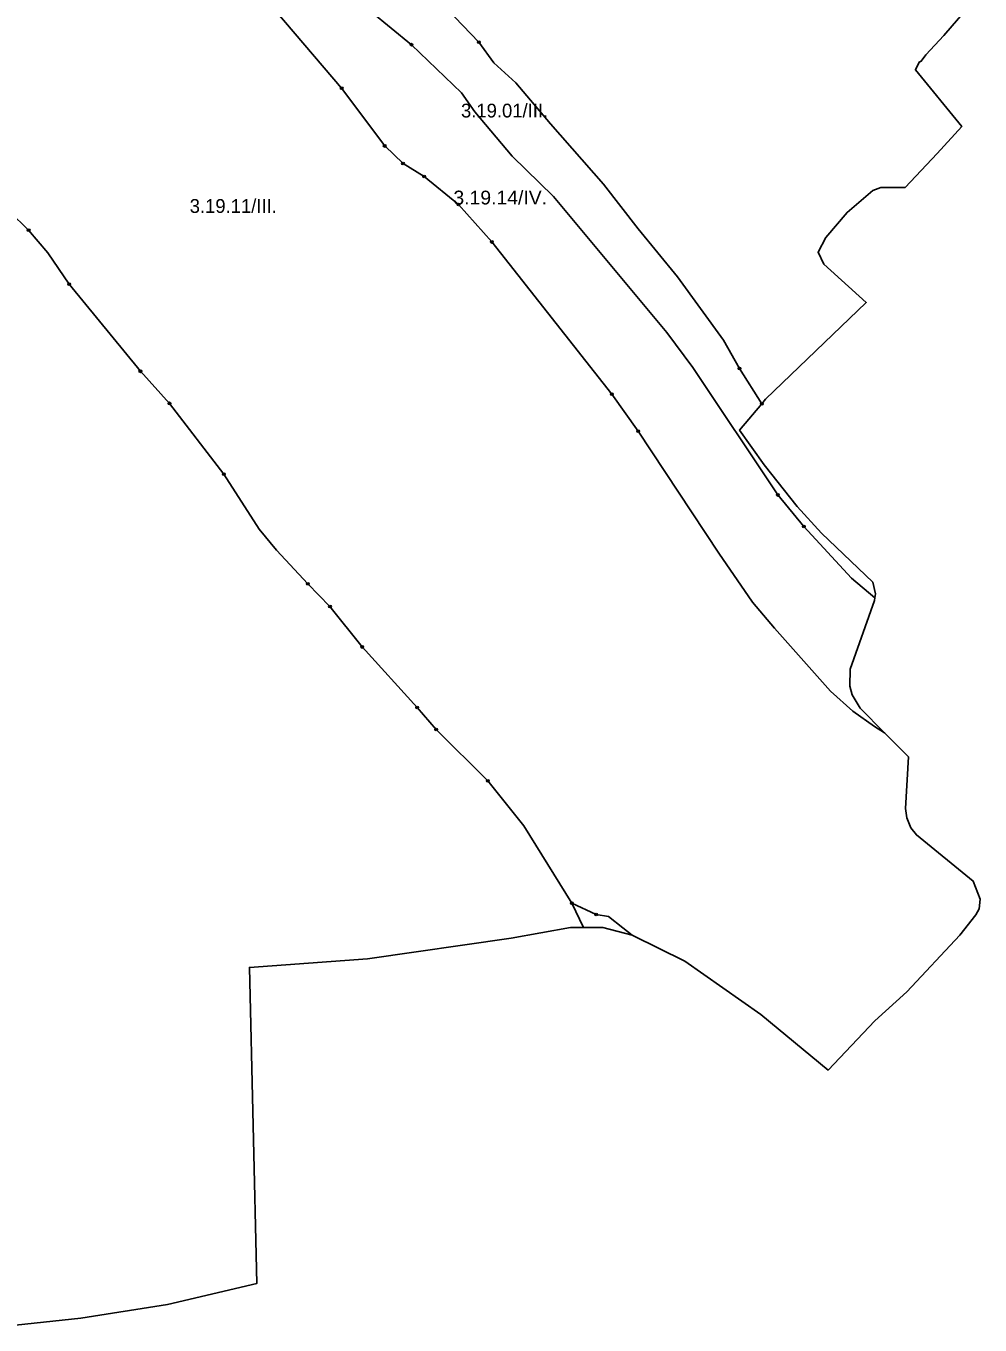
# Model space of a CAD drawing. Extents: x -650455 to -642254, y -1075222 to -1066610.
# Drawn here: x -644416 to -643724, y -1073642 to -1072701 of the extents above; entities that cross this region are included whole.
import ezdxf
from ezdxf.enums import TextEntityAlignment as Align

# ---------------------------------------------------------------- set-up
doc = ezdxf.new("R2010")
doc.units = 0
doc.header["$LTSCALE"] = 4
doc.header["$PDMODE"] = 32
doc.header["$PDSIZE"] = 2
for name, color, linetype, lineweight in [('1', 7, 'Continuous', 25), ('11', 7, 'Continuous', 13), ('13', 7, 'Continuous', 13), ('14', 7, 'Continuous', 13)]:
    doc.layers.add(name, color=color, linetype=linetype, lineweight=lineweight)
doc.layers.add('2', color=7, linetype='Continuous')

msp = doc.modelspace()

# ---------------------------------------------------------------- linework, layer by layer
at = {"layer": '1'}
for points in [[(-644133.59, -1072663.941), (-644087.515, -1072712.377), (-644076.499, -1072727.239), (-644060.762, -1072741.927), (-644035.408, -1072771.653), (-643997.027, -1072815.367), (-643971.935, -1072847.715), (-643943.434, -1072882.512), (-643910.123, -1072928.499), (-643898.495, -1072948.957)], [(-643734.991, -1072689.776), (-643750.231, -1072707.416), (-643763.214, -1072721.526), (-643766.742, -1072726.043), (-643768.011, -1072726.748), (-643770.864, -1072732.304), (-643737.297, -1072773.436), (-643755.036, -1072793.028), (-643778.183, -1072817.707), (-643795.921, -1072817.707), (-643801.762, -1072819.98), (-643820.366, -1072835.782), (-643835.725, -1072853.968), (-643841.349, -1072864.684), (-643837.239, -1072873.344), (-643806.535, -1072901.023), (-643879.504, -1072971.156), (-643882.299, -1072974.5), (-643898.495, -1072948.957), (-643910.123, -1072928.499), (-643943.434, -1072882.512), (-643971.935, -1072847.715), (-643997.027, -1072815.367), (-644035.408, -1072771.653), (-644060.762, -1072741.927), (-644076.499, -1072727.239), (-644087.515, -1072712.377), (-644133.59, -1072663.941)], [(-644234.796, -1072689.872), (-644186.973, -1072745.651), (-644155.761, -1072787.617), (-644142.471, -1072800.381), (-644127.172, -1072809.824), (-644102.167, -1072830.107), (-644078.124, -1072857.21), (-643990.959, -1072967.544), (-643971.987, -1072994.472), (-643913.497, -1073082.949), (-643888.93, -1073118.445), (-643872.93, -1073137.155), (-643832.539, -1073182.792), (-643816.189, -1073197.48), (-643800.627, -1073208.496), (-643793.212, -1073213.013), (-643775.773, -1073230.523), (-643778.031, -1073267.918), (-643777.184, -1073274.69), (-643774.079, -1073282.028), (-643769.987, -1073286.968), (-643729.064, -1073320.694)], [(-644165.902, -1072690.047), (-644136.264, -1072714.177), (-644100.069, -1072749.148), (-644090.364, -1072762.787), (-644063.262, -1072794.961), (-644033.274, -1072824.162), (-643951.179, -1072922.956), (-643932.382, -1072948.31), (-643870.57, -1073040.634), (-643851.773, -1073063.54), (-643817.151, -1073100.96), (-643800.254, -1073115.142), (-643800.608, -1073117.208), (-643818.106, -1073166.881), (-643818.53, -1073179.298), (-643816.837, -1073185.507), (-643810.91, -1073195.243), (-643793.212, -1073213.013), (-643800.627, -1073208.496), (-643816.189, -1073197.48), (-643832.539, -1073182.792), (-643872.93, -1073137.155), (-643888.93, -1073118.445), (-643913.497, -1073082.949), (-643971.987, -1072994.472), (-643990.959, -1072967.544), (-644078.124, -1072857.21), (-644102.167, -1072830.107), (-644127.172, -1072809.824), (-644142.471, -1072800.381), (-644155.761, -1072787.617), (-644186.973, -1072745.651), (-644234.796, -1072689.872)], [(-643799.762, -1073112.269), (-643800.254, -1073115.142), (-643817.151, -1073100.96), (-643851.773, -1073063.54), (-643870.57, -1073040.634), (-643932.382, -1072948.31), (-643951.179, -1072922.956), (-644033.274, -1072824.162), (-644063.262, -1072794.961), (-644090.364, -1072762.787), (-644100.069, -1072749.148), (-644136.264, -1072714.177), (-644165.902, -1072690.047)], [(-644427.764, -1072835.165), (-644413.997, -1072848.687), (-644400.183, -1072865.124), (-644384.621, -1072887.855), (-644332.951, -1072950.978), (-644311.793, -1072974.234), (-644272.363, -1073025.642), (-644246.747, -1073065.334), (-644234.157, -1073080.721), (-644211.513, -1073105.026), (-644195.427, -1073121.463), (-644172.083, -1073150.839), (-644132.216, -1073194.728), (-644118.49, -1073210.64), (-644080.896, -1073247.884), (-644054.929, -1073280.582), (-644020.045, -1073336.536), (-644011.677, -1073354.192), (-644020.886, -1073354.137), (-644064.067, -1073362.039), (-644168.209, -1073376.856), (-644253.864, -1073383.206), (-644248.437, -1073612.322), (-644313.273, -1073627.474), (-644376.209, -1073637.35), (-644423.623, -1073642.431)], [(-643729.064, -1073320.694), (-643723.984, -1073333.675), (-643724.69, -1073340.59), (-643726.947, -1073344.965), (-643738.66, -1073359.782), (-643777.043, -1073400.846), (-643800.326, -1073422.013), (-643834.173, -1073457.614), (-643882.878, -1073417.215), (-643938.194, -1073378.691), (-643975.73, -1073359.923), (-643976.242, -1073359.79), (-643983.062, -1073354.416), (-643993.414, -1073346.315), (-644002.385, -1073344.755), (-644020.045, -1073336.536), (-644054.929, -1073280.582), (-644080.896, -1073247.884), (-644118.49, -1073210.64), (-644132.216, -1073194.728), (-644172.083, -1073150.839), (-644195.427, -1073121.463), (-644211.513, -1073105.026), (-644234.157, -1073080.721), (-644246.747, -1073065.334), (-644272.363, -1073025.642), (-644311.793, -1072974.234), (-644332.951, -1072950.978), (-644384.621, -1072887.855), (-644400.183, -1072865.124), (-644413.997, -1072848.687), (-644427.764, -1072835.165)], [(-643898.495, -1072948.957), (-643882.299, -1072974.5), (-643898.324, -1072993.671), (-643880.62, -1073018.853), (-643856.489, -1073048.91), (-643838.991, -1073068.243), (-643801.737, -1073103.803), (-643799.762, -1073112.269)]]:
    msp.add_lwpolyline(points, dxfattribs=at)
msp.add_lwpolyline([(-643983.062, -1073354.416), (-643976.242, -1073359.79), (-643997.462, -1073354.278), (-644011.677, -1073354.192), (-644020.045, -1073336.536), (-644002.385, -1073344.755), (-643993.414, -1073346.315)], close=True, dxfattribs=at)
at = {"layer": '11'}
for points in [[(-644133.59, -1072663.941), (-644087.515, -1072712.377), (-644076.499, -1072727.239), (-644060.762, -1072741.927), (-644035.408, -1072771.653)], [(-643882.299, -1072974.5), (-643879.504, -1072971.156), (-643806.535, -1072901.023), (-643837.239, -1072873.344), (-643841.349, -1072864.684), (-643835.725, -1072853.968), (-643820.366, -1072835.782), (-643801.762, -1072819.98), (-643795.921, -1072817.707), (-643778.183, -1072817.707), (-643755.036, -1072793.028), (-643737.297, -1072773.436), (-643770.864, -1072732.304), (-643768.011, -1072726.748), (-643766.742, -1072726.043), (-643763.214, -1072721.526), (-643750.231, -1072707.416), (-643734.991, -1072689.776)], [(-644035.408, -1072771.653), (-643997.027, -1072815.367), (-643971.935, -1072847.715), (-643943.434, -1072882.512), (-643910.123, -1072928.499), (-643898.495, -1072948.957), (-643882.299, -1072974.5)]]:
    msp.add_lwpolyline(points, dxfattribs=at)
msp.add_point((-643882.299, -1072974.5), dxfattribs=at)
at = {"layer": '13'}
for p, q in [((-644155.761, -1072787.617), (-644186.973, -1072745.651)), ((-644142.471, -1072800.381), (-644155.761, -1072787.617)), ((-644311.793, -1072974.234), (-644272.363, -1073025.642)), ((-644195.427, -1073121.463), (-644172.083, -1073150.839)), ((-644172.083, -1073150.839), (-644132.216, -1073194.728)), ((-644132.216, -1073194.728), (-644118.49, -1073210.64)), ((-644118.49, -1073210.64), (-644080.896, -1073247.884)), ((-644020.045, -1073336.536), (-644002.385, -1073344.755))]:
    msp.add_line(p, q, dxfattribs=at)
for points in [[(-644087.515, -1072712.377), (-644133.59, -1072663.941), (-644141.983, -1072654.499), (-644148.278, -1072649.253), (-644177.392, -1072620.927), (-644195.402, -1072601.518), (-644209.565, -1072583.682), (-644221.018, -1072567.071), (-644234.482, -1072548.536), (-644249.695, -1072522.483), (-644262.896, -1072504.647), (-644270.415, -1072497.128), (-644262.896, -1072532.799), (-644259.8, -1072552.61), (-644255.953, -1072567.997), (-644245.025, -1072592.302), (-644236.282, -1072610.662), (-644215.824, -1072635.667), (-644184.262, -1072673.086), (-644165.902, -1072690.047), (-644136.264, -1072714.177)], [(-644186.973, -1072745.651), (-644234.796, -1072689.872), (-644258.227, -1072667.141), (-644304.476, -1072617.307)], [(-644136.264, -1072714.177), (-644100.069, -1072749.148), (-644090.364, -1072762.787), (-644063.262, -1072794.961), (-644033.274, -1072824.162), (-643951.179, -1072922.956), (-643932.382, -1072948.31), (-643870.57, -1073040.634), (-643851.773, -1073063.54)], [(-643898.495, -1072948.957), (-643910.123, -1072928.499), (-643943.434, -1072882.512), (-643971.935, -1072847.715), (-643997.027, -1072815.367), (-644035.408, -1072771.653), (-644060.762, -1072741.927), (-644076.499, -1072727.239), (-644087.515, -1072712.377)], [(-644102.167, -1072830.107), (-644127.172, -1072809.824), (-644142.471, -1072800.381)], [(-644424.966, -1072822.225), (-644427.764, -1072835.165), (-644413.997, -1072848.687)], [(-643971.987, -1072994.472), (-643990.959, -1072967.544), (-644078.124, -1072857.21), (-644102.167, -1072830.107)], [(-644332.951, -1072950.978), (-644384.621, -1072887.855), (-644400.183, -1072865.124), (-644413.997, -1072848.687), (-644427.764, -1072835.165)], [(-644413.997, -1072848.687), (-644400.183, -1072865.124), (-644384.621, -1072887.855)], [(-644384.621, -1072887.855), (-644332.951, -1072950.978), (-644311.793, -1072974.234)], [(-644211.513, -1073105.026), (-644234.157, -1073080.721), (-644246.747, -1073065.334), (-644272.363, -1073025.642), (-644311.793, -1072974.234), (-644332.951, -1072950.978)], [(-643851.773, -1073063.54), (-643817.151, -1073100.96), (-643800.254, -1073115.142), (-643799.762, -1073112.269), (-643801.737, -1073103.803), (-643838.991, -1073068.243), (-643856.489, -1073048.91), (-643880.62, -1073018.853), (-643898.324, -1072993.671), (-643882.299, -1072974.5), (-643898.495, -1072948.957)], [(-644002.385, -1073344.755), (-643993.414, -1073346.315), (-643983.062, -1073354.416), (-643976.242, -1073359.79), (-643975.73, -1073359.923), (-643938.194, -1073378.691), (-643882.878, -1073417.215), (-643834.173, -1073457.614), (-643800.326, -1073422.013), (-643777.043, -1073400.846), (-643738.66, -1073359.782), (-643726.947, -1073344.965), (-643724.69, -1073340.59), (-643723.984, -1073333.675), (-643729.064, -1073320.694), (-643769.987, -1073286.968), (-643774.079, -1073282.028), (-643777.184, -1073274.69), (-643778.031, -1073267.918), (-643775.773, -1073230.523), (-643793.212, -1073213.013), (-643800.627, -1073208.496), (-643816.189, -1073197.48), (-643832.539, -1073182.792), (-643872.93, -1073137.155), (-643888.93, -1073118.445), (-643913.497, -1073082.949), (-643971.987, -1072994.472)], [(-644272.363, -1073025.642), (-644246.747, -1073065.334), (-644234.157, -1073080.721), (-644211.513, -1073105.026), (-644195.427, -1073121.463)], [(-644423.623, -1073642.431), (-644376.209, -1073637.35), (-644313.273, -1073627.474), (-644248.437, -1073612.322), (-644253.864, -1073383.206), (-644168.209, -1073376.856), (-644064.067, -1073362.039), (-644020.886, -1073354.137), (-644011.677, -1073354.192), (-644020.045, -1073336.536), (-644054.929, -1073280.582), (-644080.896, -1073247.884), (-644118.49, -1073210.64), (-644132.216, -1073194.728), (-644172.083, -1073150.839), (-644195.427, -1073121.463), (-644211.513, -1073105.026)], [(-644080.896, -1073247.884), (-644054.929, -1073280.582), (-644020.045, -1073336.536)]]:
    msp.add_lwpolyline(points, dxfattribs=at)
for p in [(-644136.264, -1072714.177), (-644087.515, -1072712.377), (-644186.973, -1072745.651), (-644155.761, -1072787.617), (-644142.471, -1072800.381), (-644102.167, -1072830.107), (-644413.997, -1072848.687), (-644384.621, -1072887.855), (-644332.951, -1072950.978), (-643898.495, -1072948.957), (-644311.793, -1072974.234), (-643971.987, -1072994.472), (-644272.363, -1073025.642), (-643851.773, -1073063.54), (-644211.513, -1073105.026), (-644195.427, -1073121.463), (-644172.083, -1073150.839), (-644132.216, -1073194.728), (-644118.49, -1073210.64), (-644080.896, -1073247.884), (-644020.045, -1073336.536), (-644002.385, -1073344.755)]:
    msp.add_point(p, dxfattribs=at)
at = {"layer": '14'}
for p, q in [((-644078.124, -1072857.21), (-643990.959, -1072967.544)), ((-643990.959, -1072967.544), (-643971.987, -1072994.472))]:
    msp.add_line(p, q, dxfattribs=at)
for points in [[(-644258.227, -1072667.141), (-644234.796, -1072689.872), (-644186.973, -1072745.651), (-644155.761, -1072787.617), (-644142.471, -1072800.381), (-644127.172, -1072809.824)], [(-643870.57, -1073040.634), (-643932.382, -1072948.31), (-643951.179, -1072922.956), (-644033.274, -1072824.162), (-644063.262, -1072794.961), (-644090.364, -1072762.787), (-644100.069, -1072749.148), (-644136.264, -1072714.177), (-644165.902, -1072690.047)], [(-644127.172, -1072809.824), (-644102.167, -1072830.107), (-644078.124, -1072857.21)], [(-643971.987, -1072994.472), (-643913.497, -1073082.949), (-643888.93, -1073118.445), (-643872.93, -1073137.155), (-643832.539, -1073182.792), (-643816.189, -1073197.48), (-643800.627, -1073208.496), (-643793.212, -1073213.013), (-643810.91, -1073195.243), (-643816.837, -1073185.507), (-643818.53, -1073179.298), (-643818.106, -1073166.881), (-643800.608, -1073117.208), (-643800.254, -1073115.142), (-643817.151, -1073100.96), (-643851.773, -1073063.54), (-643870.57, -1073040.634)]]:
    msp.add_lwpolyline(points, dxfattribs=at)
for p in [(-644127.172, -1072809.824), (-644078.124, -1072857.21), (-643990.959, -1072967.544), (-643971.987, -1072994.472), (-643870.57, -1073040.634)]:
    msp.add_point(p, dxfattribs=at)

# ---------------------------------------------------------------- texts
at = {"layer": '2'}
for s, p in [('3.19.01/III.', (-644068.816, -1072766.968)), ('3.19.11/III.', (-644265.576, -1072836.138))]:
    msp.add_text(s, height=10, dxfattribs=at).set_placement(p, align=Align.CENTER)
at = {"layer": '2', "width": 1.05}
msp.add_text('3.19.14/IV.', height=10, dxfattribs=at).set_placement((-644071.954, -1072830.022), align=Align.CENTER)

doc.saveas('drawing.dxf')
